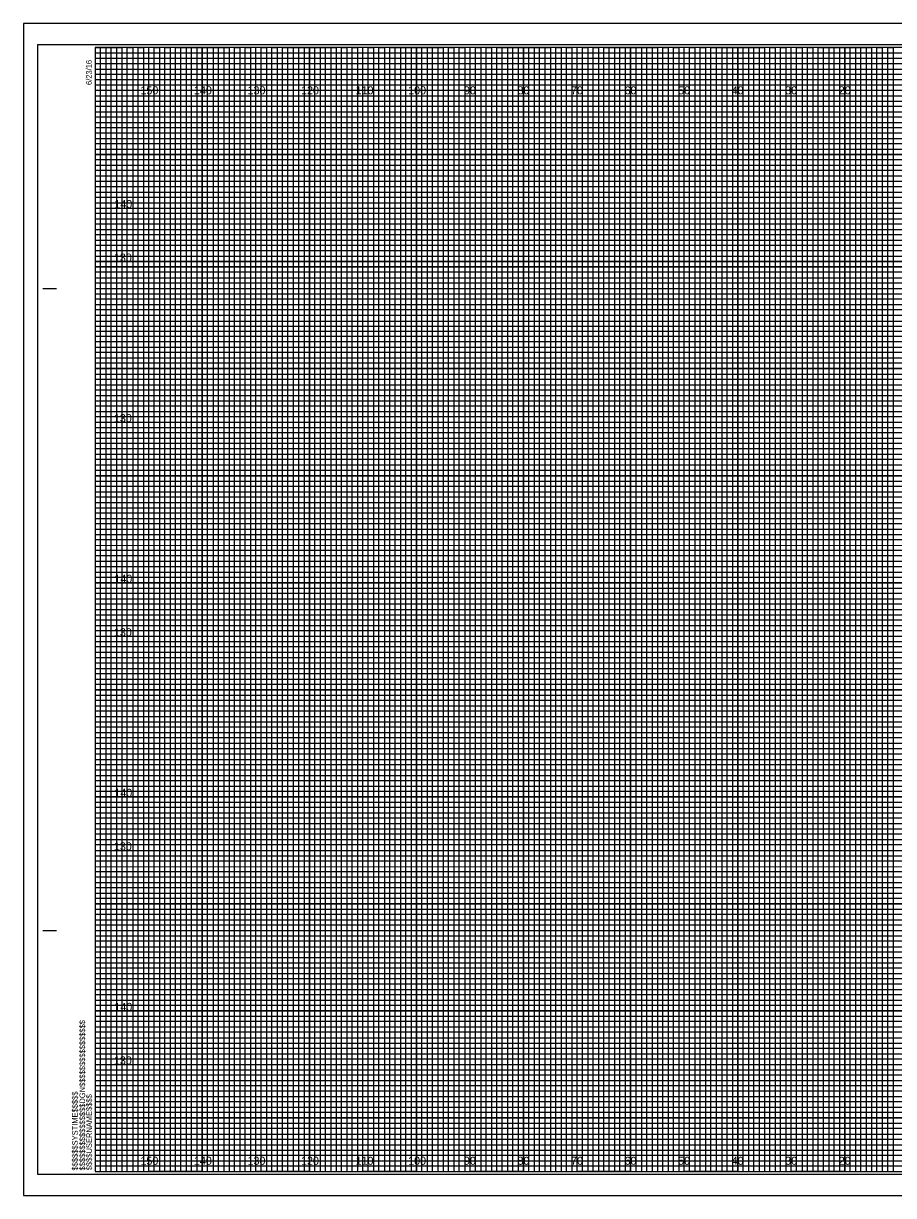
# Model space of a CAD drawing. Extents: x -13 to 329, y -17 to 10994.
# Drawn here: x -13.4 to 149.1, y 1535.5 to 1754.5 of the extents above; entities that cross this region are included whole.
import ezdxf

# ---------------------------------------------------------------- set-up
doc = ezdxf.new("R2010")
doc.units = 0
for name, color, linetype in [('Prop XS Elevation Labels', 7, 'Continuous'), ('Prop XS Offset Labels', 7, 'Continuous'), ('Sheet Cross Section CELL', 7, 'Continuous'), ('Sheet Cross Section Grid Major CELL', 7, 'Continuous'), ('Sheet Cross Section Grid Middle CELL', 7, 'Continuous'), ('Sheet Cross Section Grid Minor 1 CELL', 7, 'Continuous'), ('Sheet Cross Section Grid Minor 2 CELL', 7, 'Continuous'), ('Sheet Cutting Line CELL', 7, 'Continuous'), ('Sheet DOT Grid CELL', 7, 'Continuous'), ('Sheet Plot Border Inside CELL', 7, 'Continuous'), ('Sheet Plot Border Outside CELL', 7, 'Continuous')]:
    doc.layers.add(name, color=color, linetype=linetype)

msp = doc.modelspace()

# ---------------------------------------------------------------- linework, layer by layer
at = {"layer": 'Sheet Cross Section CELL'}
for p, q in [((-9.8, 1705), (-7.3, 1705)), ((-9.7, 1705), (-7.2, 1705)), ((-9.8, 1585), (-7.3, 1585)), ((-9.7, 1585), (-7.2, 1585)), ((0, 1540), (0, 1540)), ((0, 1540), (0, 1540)), ((0, 1540), (0, 1540)), ((0, 1540), (0, 1540)), ((0, 1540), (0, 1540)), ((0, 1540), (0, 1540)), ((0, 1540), (0, 1540))]:
    msp.add_line(p, q, dxfattribs=at)
msp.add_lwpolyline([(320, 1750), (0, 1750), (0, 1540), (320, 1540)], close=True, dxfattribs=at)
at = {"layer": 'Sheet Cross Section Grid Major CELL'}
for p, q in [((10, 1750), (0, 1750)), ((10, 1540), (10, 1750)), ((30, 1750), (20, 1750)), ((20, 1750), (20, 1540)), ((30, 1540), (30, 1750)), ((50, 1750), (40, 1750)), ((40, 1750), (40, 1540)), ((50, 1540), (50, 1750)), ((70, 1750), (60, 1750)), ((60, 1750), (60, 1540)), ((70, 1540), (70, 1750)), ((90, 1750), (80, 1750)), ((80, 1750), (80, 1540)), ((90, 1540), (90, 1750)), ((110, 1750), (100, 1750)), ((100, 1750), (100, 1540)), ((110, 1540), (110, 1750)), ((130, 1750), (120, 1750)), ((120, 1750), (120, 1540)), ((130, 1540), (130, 1750)), ((150, 1750), (140, 1750)), ((140, 1750), (140, 1540)), ((20, 1540), (10, 1540)), ((40, 1540), (30, 1540)), ((60, 1540), (50, 1540)), ((80, 1540), (70, 1540)), ((100, 1540), (90, 1540)), ((120, 1540), (110, 1540)), ((140, 1540), (130, 1540))]:
    msp.add_line(p, q, dxfattribs=at)
for points in [[(0, 1740), (320, 1740), (320, 1730), (0, 1730)], [(0, 1720), (320, 1720), (320, 1710), (0, 1710)], [(0, 1700), (320, 1700), (320, 1690), (0, 1690)], [(0, 1680), (320, 1680), (320, 1670), (0, 1670)], [(0, 1660), (320, 1660), (320, 1650), (0, 1650)], [(0, 1640), (320, 1640), (320, 1630), (0, 1630)], [(0, 1620), (320, 1620), (320, 1610), (0, 1610)], [(0, 1600), (320, 1600), (320, 1590), (0, 1590)], [(0, 1580), (320, 1580), (320, 1570), (0, 1570)], [(0, 1560), (320, 1560), (320, 1550), (0, 1550)]]:
    msp.add_lwpolyline(points, dxfattribs=at)
at = {"layer": 'Sheet Cross Section Grid Middle CELL'}
for points in [[(0, 1750), (5, 1750), (5, 1540), (15, 1540), (15, 1750), (25, 1750), (25, 1540), (35, 1540), (35, 1750), (45, 1750), (45, 1540), (55, 1540), (55, 1750), (65, 1750), (65, 1540), (75, 1540), (75, 1750), (85, 1750), (85, 1540), (95, 1540), (95, 1750), (105, 1750), (105, 1540), (115, 1540), (115, 1750), (125, 1750), (125, 1540), (135, 1540), (135, 1750), (145, 1750), (145, 1540), (155, 1540)], [(0, 1745), (275, 1745)], [(0, 1725), (320, 1725), (320, 1735), (0, 1735)], [(0, 1705), (320, 1705), (320, 1715), (0, 1715)], [(0, 1685), (320, 1685), (320, 1695), (0, 1695)], [(0, 1665), (320, 1665), (320, 1675), (0, 1675)], [(0, 1645), (320, 1645), (320, 1655), (0, 1655)], [(0, 1625), (320, 1625), (320, 1635), (0, 1635)], [(0, 1605), (320, 1605), (320, 1615), (0, 1615)], [(0, 1585), (320, 1585), (320, 1595), (0, 1595)], [(0, 1565), (320, 1565), (320, 1575), (0, 1575)], [(0, 1545), (320, 1545), (320, 1555), (0, 1555)]]:
    msp.add_lwpolyline(points, dxfattribs=at)
at = {"layer": 'Sheet Cross Section Grid Minor 1 CELL'}
for p, q in [((0, 1749), (260, 1749)), ((260, 1747.98), (0, 1747.98)), ((0, 1747.98), (0, 1747)), ((0, 1747), (260, 1747)), ((260, 1745.89), (0, 1745.89)), ((0, 1745.89), (0, 1744)), ((0, 1744), (320, 1744))]:
    msp.add_line(p, q, dxfattribs=at)
for points in [[(0, 1743), (270, 1743), (320, 1743), (320, 1742), (0, 1742)], [(0, 1741), (320, 1741), (320, 1739), (0, 1739)], [(0, 1738), (320, 1738), (320, 1737), (0, 1736.98)], [(0, 1736), (320, 1736), (320, 1734), (0, 1734)], [(0, 1733), (320, 1733), (320, 1732), (0, 1732)], [(0, 1731), (320, 1731), (320, 1729), (0, 1729)], [(0, 1728), (320, 1728), (320, 1727), (0, 1727)], [(0, 1726), (320, 1726), (320, 1724), (0, 1724)], [(0, 1723), (320, 1723), (320, 1722), (0, 1722)], [(0, 1721), (320, 1721), (320, 1719), (0, 1719)], [(0, 1718), (320, 1718), (320, 1717), (0, 1717)], [(0, 1716), (320, 1716), (320, 1713.95), (320, 1713), (320, 1712), (0, 1712)], [(0, 1714), (320, 1714), (320, 1713), (0, 1713)], [(0, 1711), (320, 1711), (320, 1709), (0, 1709.03)], [(0, 1709.03), (320, 1709), (320, 1708), (0, 1708)], [(0, 1707), (320, 1707), (320, 1706), (0, 1706)], [(0, 1704), (320, 1704), (320, 1703), (0, 1703)], [(0, 1702), (320, 1702), (320, 1701), (0, 1701)], [(-0.07, 1698.89), (320, 1698.89), (320, 1697.88), (-0.07, 1697.88)], [(0, 1697), (320, 1697), (320, 1696), (0, 1696)], [(0, 1694), (320, 1694), (320, 1693), (0, 1693)], [(0, 1692), (320, 1692), (320, 1691), (0, 1691)], [(0, 1689), (320, 1689), (320, 1688), (0, 1688)], [(0, 1687), (320, 1687), (320, 1686), (0, 1686)], [(0, 1684), (320, 1684), (320, 1683), (0, 1683)], [(0, 1682), (320, 1682), (320, 1681), (0, 1681)], [(0, 1679), (320, 1679), (319.99, 1677.98), (0, 1678)], [(0, 1677), (320, 1677), (320, 1676), (0, 1676)], [(0, 1674), (320, 1674), (320, 1673), (0, 1673)], [(0, 1672), (320, 1672), (320, 1671), (0, 1671)], [(0, 1669), (320, 1669), (320, 1668), (0, 1668)], [(0, 1667), (320, 1667), (320, 1666), (0, 1666)], [(0, 1664), (320, 1664), (320, 1663), (0, 1663)], [(0, 1662), (320, 1662), (320, 1661), (0, 1661)], [(0, 1659), (320, 1659), (320, 1658), (0, 1658)], [(0, 1656.99), (320.07, 1656.91), (320, 1656), (0, 1656)], [(0, 1654), (320, 1654), (320, 1653), (0, 1653)], [(0, 1652), (320, 1652), (320, 1651), (0, 1651)], [(0, 1649), (320, 1649), (320, 1648), (0, 1648)], [(0, 1647), (320, 1647), (320, 1646), (0, 1646)], [(0, 1644), (320, 1644), (320, 1643), (0, 1643)], [(0, 1642), (320, 1642), (320, 1641), (0, 1641)], [(0, 1639), (320, 1639), (320, 1638), (0, 1638)], [(0, 1637), (320, 1637), (320, 1636), (0, 1636)], [(0, 1634), (320, 1634), (320, 1633), (0, 1633)], [(0, 1632), (320, 1632), (320, 1631), (0, 1631)], [(0, 1629), (320, 1629), (320, 1628), (0, 1628)], [(0, 1627), (320, 1627), (320, 1626), (0, 1626)], [(0, 1624), (320, 1624), (320, 1623), (0, 1623)], [(0, 1622), (320, 1622), (320, 1621), (0, 1621)], [(0, 1619), (320, 1619), (319.99, 1617.98), (0, 1618)], [(0, 1617), (320, 1617), (320, 1616), (0, 1616)], [(0, 1614), (320, 1614), (320, 1613), (0, 1613)], [(0, 1612), (320, 1612), (320, 1611), (0, 1611)], [(0, 1609), (320, 1609), (320, 1608), (0, 1608)], [(0, 1607), (320, 1607), (320, 1606), (0, 1606)], [(0, 1604), (320, 1604), (320, 1603), (0, 1603)], [(0, 1602), (320, 1602), (320, 1601), (0, 1601)], [(0, 1599), (320, 1599), (320, 1598), (0, 1598)], [(0, 1596.99), (320.07, 1596.91), (320, 1596), (0, 1596)], [(0, 1594), (320, 1594), (320, 1593), (0, 1593)], [(0, 1592), (320, 1592), (320, 1591), (0, 1591)], [(0, 1589), (320, 1589), (320, 1588), (0, 1588)], [(0, 1587), (320, 1587), (320, 1586), (0, 1586)], [(0, 1584), (320, 1584), (320, 1583), (0, 1583)], [(0, 1582), (320, 1582), (320, 1581), (0, 1581)], [(0, 1579), (320, 1579), (320, 1578), (0, 1578)], [(0, 1577), (320, 1577), (320, 1576), (0, 1576)], [(0, 1574), (320, 1574), (320, 1573), (0, 1573)], [(0, 1572), (320, 1572), (320, 1571), (0, 1571)], [(0, 1569), (320, 1569), (320, 1568), (0, 1568)], [(0, 1567), (320, 1567), (320, 1566), (0, 1566)], [(0, 1564), (320, 1564), (320, 1563), (0, 1563)], [(0, 1562), (320, 1562), (320, 1561), (0, 1561)], [(0, 1559), (320, 1559), (320, 1558), (0, 1558)], [(0, 1557), (320, 1557), (320, 1556), (0, 1556)], [(0, 1554), (320, 1554), (320, 1553), (0, 1553)], [(0, 1552), (320, 1552), (320, 1551), (0, 1551)], [(0, 1549), (320, 1549), (320, 1548), (0, 1548)], [(0, 1547), (320, 1547), (320, 1546), (0, 1546)], [(0, 1544), (320, 1544), (320, 1543), (0, 1543)], [(0, 1542), (320, 1542), (320, 1541), (0, 1541)]]:
    msp.add_lwpolyline(points, dxfattribs=at)
at = {"layer": 'Sheet Cross Section Grid Minor 2 CELL'}
for points in [[(0, 1540), (1, 1540), (1, 1750), (2, 1750), (2, 1540)], [(2, 1540), (3, 1540), (3, 1750), (4, 1750), (4, 1540)], [(5, 1540), (6, 1540), (6, 1750), (7, 1750), (7, 1540)], [(7, 1540), (8, 1540), (8, 1750), (9, 1750), (9, 1540)], [(10, 1540), (11, 1540), (11, 1750), (12, 1750), (12, 1540)], [(12, 1540), (13, 1540), (13, 1750), (14, 1750), (14, 1540)], [(15, 1540), (16, 1540), (16, 1750), (17, 1750), (17, 1540)], [(17, 1540), (18, 1540), (18, 1750), (19, 1750), (19, 1540)], [(20, 1540), (21, 1540), (21, 1750), (22, 1750), (22, 1540)], [(22, 1540), (23, 1540), (23, 1750), (24, 1750), (24, 1540)], [(25, 1540), (26, 1540), (26, 1750), (27, 1750), (27, 1540)], [(27, 1540), (28, 1540), (28, 1750), (29, 1750), (29, 1540)], [(30, 1540), (31, 1540), (31, 1750), (32, 1750), (32, 1540)], [(32, 1540), (33, 1540), (33, 1750), (34, 1750), (34, 1540)], [(35, 1540), (36, 1540), (36, 1750), (37, 1750), (37, 1540)], [(37, 1540), (38, 1540), (38, 1750), (39, 1750), (39, 1540)], [(40, 1540), (41, 1540), (41, 1750), (42, 1750), (42, 1540)], [(42, 1540), (43, 1540), (43, 1750), (44, 1750), (44, 1540)], [(45, 1540), (46, 1540), (46, 1750), (47, 1750), (47, 1540)], [(47, 1540), (48, 1540), (48, 1750), (49, 1750), (49, 1540)], [(50, 1540), (51, 1540), (51, 1750), (52, 1750), (52, 1540)], [(52, 1540), (53, 1540), (53, 1750), (54, 1750), (54, 1540)], [(55, 1540), (56, 1540), (56, 1750), (57, 1750), (57, 1540)], [(57, 1540), (58, 1540), (58, 1750), (59, 1750), (59, 1540)], [(60, 1540), (61, 1540), (61, 1750), (62, 1750), (62, 1540)], [(62, 1540), (63, 1540), (63, 1750), (64, 1750), (64, 1540)], [(65, 1540), (66, 1540), (66, 1750), (67, 1750), (67, 1540)], [(67, 1540), (68, 1540), (68, 1750), (69, 1750), (69, 1540)], [(70, 1540), (71, 1540), (71, 1750), (72, 1750), (72, 1540)], [(72, 1540), (73, 1540), (73, 1750), (74, 1750), (74, 1540)], [(75, 1540), (76, 1540), (76, 1750), (77, 1750), (77, 1540)], [(77, 1540), (78, 1540), (78, 1750), (79, 1750), (79, 1540)], [(80, 1540), (81, 1540), (81, 1750), (82, 1750), (82, 1540)], [(82, 1540), (83, 1540), (83, 1750), (84, 1750), (84, 1540)], [(85, 1540), (86, 1540), (86, 1750), (87, 1750), (87, 1540)], [(87, 1540), (88, 1540), (88, 1750), (89, 1750), (89, 1540)], [(90, 1540), (91, 1540), (91, 1750), (92, 1750), (92, 1540)], [(92, 1540), (93, 1540), (93, 1750), (94, 1750), (94, 1540)], [(95, 1540), (96, 1540), (96, 1750), (97, 1750), (97, 1540)], [(97, 1540), (98, 1540), (98, 1750), (99, 1750), (99, 1540)], [(100, 1540), (101, 1540), (101, 1750), (102, 1750), (102, 1540)], [(102, 1540), (103, 1540), (103, 1750), (104, 1750), (104, 1540)], [(105, 1540), (106, 1540), (106, 1750), (107, 1750), (107, 1540)], [(107, 1540), (108, 1540), (108, 1750), (109, 1750), (109, 1540)], [(110, 1540), (111, 1540), (111, 1750), (112, 1750), (112, 1540)], [(112, 1540), (113, 1540), (113, 1750), (114, 1750), (114, 1540)], [(115, 1540), (116, 1540), (116, 1750), (117, 1750), (117, 1540)], [(117, 1540), (118, 1540), (118, 1750), (119, 1750), (119, 1540)], [(120, 1540), (121, 1540), (121, 1750), (122, 1750), (122, 1540)], [(122, 1540), (123, 1540), (123, 1750), (124, 1750), (124, 1540)], [(125, 1540), (126, 1540), (126, 1750), (127, 1750), (127, 1540)], [(127, 1540), (128, 1540), (128, 1750), (129, 1750), (129, 1540)], [(130, 1540), (131, 1540), (131, 1750), (132, 1750), (132, 1540)], [(132, 1540), (133, 1540), (133, 1750), (134, 1750), (134, 1540)], [(135, 1540), (136, 1540), (136, 1750), (137, 1750), (137, 1540)], [(137, 1540), (138, 1540), (138, 1750), (139, 1750), (139, 1540)], [(140, 1540), (141, 1540), (141, 1750), (142, 1750), (142, 1540)], [(142, 1540), (143, 1540), (143, 1750), (144, 1750), (144, 1540)], [(145, 1540), (146, 1540), (146, 1750), (147, 1750), (147, 1540)], [(147, 1540), (148, 1540), (148, 1750), (149, 1750), (149, 1540)]]:
    msp.add_lwpolyline(points, dxfattribs=at)
at = {"layer": 'Sheet Cutting Line CELL'}
for p, q in [((323.3, 1754.5), (-13.4, 1754.5)), ((-13.4, 1754.5), (-13.4, 1535.5)), ((-13.4, 1535.5), (323.3, 1535.5))]:
    msp.add_line(p, q, dxfattribs=at)
at = {"layer": 'Sheet DOT Grid CELL'}
for p, q in [((10, 1540), (10, 1750)), ((20, 1540), (20, 1750)), ((30, 1540), (30, 1750)), ((40, 1540), (40, 1750)), ((50, 1540), (50, 1750)), ((60, 1540), (60, 1750)), ((70, 1540), (70, 1750)), ((80, 1540), (80, 1750)), ((90, 1540), (90, 1750)), ((100, 1540), (100, 1750)), ((110, 1540), (110, 1750)), ((120, 1540), (120, 1750)), ((130, 1540), (130, 1750)), ((140, 1540), (140, 1750)), ((0, 1740), (320, 1740)), ((0, 1730), (320, 1730)), ((0, 1720), (320, 1720)), ((0, 1710), (320, 1710)), ((0, 1700), (320, 1700)), ((0, 1690), (320, 1690)), ((0, 1680), (320, 1680)), ((0, 1670), (320, 1670)), ((0, 1660), (320, 1660)), ((0, 1650), (320, 1650)), ((0, 1640), (320, 1640)), ((0, 1630), (320, 1630)), ((0, 1620), (320, 1620)), ((0, 1610), (320, 1610)), ((0, 1600), (320, 1600)), ((0, 1590), (320, 1590)), ((0, 1580), (320, 1580)), ((0, 1570), (320, 1570)), ((0, 1560), (320, 1560)), ((0, 1550), (320, 1550))]:
    msp.add_line(p, q, dxfattribs=at)
at = {"layer": 'Sheet Plot Border Inside CELL'}
msp.add_lwpolyline([(-10.8, 1539.5), (322.4, 1539.5), (322.4, 1750.5), (-10.8, 1750.5)], close=True, dxfattribs=at)
at = {"layer": 'Sheet Plot Border Outside CELL'}
msp.add_lwpolyline([(-13.4, 1535.5), (323.3, 1535.5), (323.3, 1754.5), (-13.4, 1754.5)], close=True, dxfattribs=at)

# ---------------------------------------------------------------- texts
at = {"layer": 'Prop XS Elevation Labels'}
for s, p in [('140', (3.57, 1720)), ('130', (3.49, 1710)), ('130', (3.49, 1680)), ('140', (3.57, 1650)), ('130', (3.49, 1640)), ('140', (3.57, 1610)), ('130', (3.49, 1600)), ('140', (3.57, 1570)), ('130', (3.49, 1560))]:
    msp.add_text(s, height=1.5, dxfattribs=at).set_placement(p)
at = {"layer": 'Prop XS Offset Labels'}
for s, p in [('150', (8.44, 1741.25)), ('140', (18.44, 1741.25)), ('130', (28.44, 1741.25)), ('120', (38.44, 1741.25)), ('110', (48.62, 1741.25)), ('100', (58.44, 1741.25)), ('90', (68.86, 1741.25)), ('80', (78.86, 1741.25)), ('70', (88.86, 1741.25)), ('60', (98.86, 1741.25)), ('50', (108.86, 1741.25)), ('40', (118.86, 1741.25)), ('30', (128.86, 1741.25)), ('20', (138.86, 1741.25)), ('150', (8.44, 1541.25)), ('140', (18.44, 1541.25)), ('130', (28.44, 1541.25)), ('120', (38.44, 1541.25)), ('110', (48.62, 1541.25)), ('100', (58.44, 1541.25)), ('90', (68.86, 1541.25)), ('80', (78.86, 1541.25)), ('70', (88.86, 1541.25)), ('60', (98.86, 1541.25)), ('50', (108.86, 1541.25)), ('40', (118.86, 1541.25)), ('30', (128.86, 1541.25)), ('20', (138.86, 1541.25))]:
    msp.add_text(s, height=1.5, dxfattribs=at).set_placement(p)
at = {"layer": 'Sheet Cross Section CELL'}
for s, p in [('6/23/16', (-0.65, 1743)), ('$$$$$$$$$$$$$$$$DGN$$$$$$$$$$$$$$$$', (-1.88, 1540.18)), ('$$$$$$SYSTIME$$$$$', (-3.26, 1540.18)), ('$$$$USERNAME$$$$', (-0.62, 1540.23))]:
    msp.add_text(s, height=1.05, rotation=90, dxfattribs=at).set_placement(p)

doc.saveas('drawing.dxf')
